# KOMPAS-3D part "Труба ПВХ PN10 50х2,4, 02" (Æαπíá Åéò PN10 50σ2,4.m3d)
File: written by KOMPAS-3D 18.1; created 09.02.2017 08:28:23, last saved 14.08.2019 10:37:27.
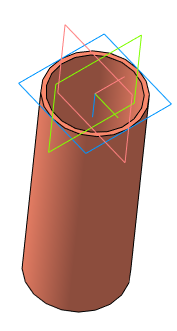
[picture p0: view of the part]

Document properties: Автор: Милов; Организация: Милов; Полное имя файла: D:\Мембранные насосы\Мембранный электропривод\А302-00.00.000 - ASTRA-302 (МЭ200)\3Д ПВХ\Отработка\Труба ПВХ PN10 50х2,4.m3d

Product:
- Part/product: Труба ПВХ PN10 50х2,4  | designation 02
    Масса: 0.340305
    Раздел спецификации: Прочие изделия
- Part/product: Труба ПВХ PN10 50х2,4
    Масса: 0.340305
    Раздел спецификации: Прочие изделия
- Part/product: Труба ПВХ PN10 50х2,4  | designation 01
    Масса: 0.335173
    Раздел спецификации: Прочие изделия

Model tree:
1. Эскиз:1
2. Операция выдавливания:9  (labels: L+88)
     Расстояние 2 = 27

Expressions: 50-2.4*2; L-27-27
